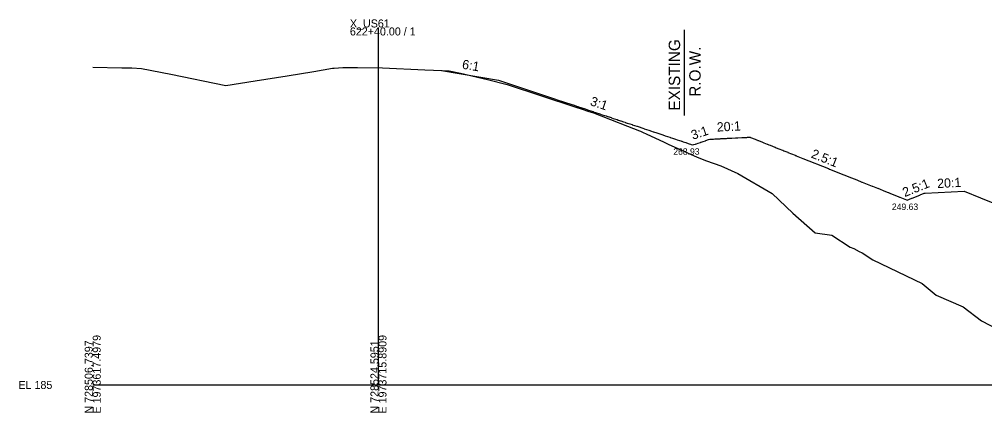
# Model space of a CAD drawing. Extents: x -26 to 1629, y -25 to 9635.
# Drawn here: x -25.7 to 312.2, y 5990.3 to 6127.8 of the extents above; entities that cross this region are included whole.
import ezdxf

# ---------------------------------------------------------------- set-up
doc = ezdxf.new("R2010")
doc.units = 0
for name, color, linetype in [('Default', 7, 'Continuous'), ('Draft_XS_Grid', 7, 'Continuous'), ('DTM CONTOURS_MAJOR', 7, 'Continuous'), ('DTM_X_GROUND', 7, 'Continuous'), ('XS_CELL', 7, 'Continuous'), ('XS_P_GROUND', 7, 'Continuous'), ('XS_P_TX_DCH', 7, 'Continuous'), ('XS_P_TX_FS_BS', 7, 'Continuous'), ('XS_X_ROW', 7, 'Continuous')]:
    doc.layers.add(name, color=color, linetype=linetype)

msp = doc.modelspace()

# ---------------------------------------------------------------- linework, layer by layer
at = {"layer": 'DTM_X_GROUND'}
msp.add_lwpolyline([(0, 6111.11), (10.2, 6110.92), (13.06, 6110.87), (13.65, 6110.85), (17.07, 6110.7), (27.36, 6108.64), (46.63, 6104.73), (56.89, 6106.31), (68.08, 6108.05), (77.42, 6109.59), (83.94, 6110.78), (84.49, 6110.81), (87.52, 6111), (92.64, 6110.94), (101.44, 6110.83), (116.19, 6110.19), (122.29, 6109.92), (124.75, 6109.8), (125.34, 6109.77), (128.7, 6109.01), (138.15, 6106.82), (138.16, 6106.81), (145.02, 6105.02), (169.03, 6097.18), (169.04, 6097.18), (171.3, 6096.44), (173.28, 6095.72), (175.2, 6095.1), (187.13, 6090.5), (191.38, 6088.82), (191.66, 6088.76), (192.43, 6088.39), (193.86, 6087.74), (199.8, 6084.97), (201.44, 6084.2), (211.49, 6079.7), (214.81, 6078.34), (219.83, 6076.62), (225.78, 6073.91), (237.78, 6066.91), (245.03, 6060.09), (252.79, 6053.2), (258.62, 6052.4), (265.04, 6048.19), (266.36, 6047.68), (268.26, 6046.69), (269.25, 6046.17), (272.97, 6043.73), (290.25, 6035.48), (295.22, 6031.45), (304.6, 6027.33), (311, 6022.42), (323.13, 6016.13)], dxfattribs=at)
at = {"layer": 'XS_CELL'}
for p, q in [((100, 6000), (100, 6125)), ((0, 6000), (100, 6000)), ((100, 6000), (550, 6000))]:
    msp.add_line(p, q, dxfattribs=at)
at = {"layer": 'XS_P_GROUND'}
for points in [[(122, 6109.93), (142, 6106.6)], [(142, 6106.6), (161.93, 6099.96), (162.54, 6099.75), (167.64, 6098.05), (167.65, 6098.05), (167.65, 6098.05), (168.04, 6097.92), (168.08, 6097.91), (169.61, 6097.4), (169.77, 6097.35), (169.96, 6097.28), (171.19, 6096.87), (171.9, 6096.63), (171.98, 6096.61), (173.46, 6096.11), (173.56, 6096.08), (175.09, 6095.57), (175.14, 6095.55), (175.16, 6095.55), (175.93, 6095.29), (175.97, 6095.28), (177.52, 6094.76), (177.65, 6094.72), (177.66, 6094.71), (178.32, 6094.49), (179.66, 6094.05), (179.92, 6093.96), (180.67, 6093.71), (180.72, 6093.69), (181.38, 6093.47), (181.41, 6093.46), (181.52, 6093.43), (182.13, 6093.22), (182.15, 6093.22), (182.18, 6093.21), (183.52, 6092.76), (183.53, 6092.76), (183.93, 6092.62), (183.95, 6092.62), (184.74, 6092.35), (184.78, 6092.34), (185.7, 6092.03), (186.28, 6091.84), (186.37, 6091.81), (187.04, 6091.59), (188, 6091.27), (188.76, 6091.01), (188.82, 6090.99), (190.38, 6090.47), (190.46, 6090.45), (190.52, 6090.43), (192.92, 6089.63), (192.96, 6089.61), (194.57, 6089.08), (194.61, 6089.06), (195.55, 6088.75), (196.13, 6088.56), (196.22, 6088.53), (196.56, 6088.41), (197.05, 6088.25), (199.21, 6087.53), (199.54, 6087.42), (200.34, 6087.15), (200.37, 6087.14), (201.98, 6086.61), (202.03, 6086.59), (202.06, 6086.58), (202.87, 6086.31), (202.95, 6086.28), (204, 6085.93), (204.54, 6085.75), (205.34, 6085.49), (205.38, 6085.47), (205.4, 6085.47), (205.82, 6085.33), (206.08, 6085.24), (206.22, 6085.2), (206.61, 6085.06), (207.05, 6084.92), (207.54, 6084.75), (207.77, 6084.68), (208.74, 6084.36), (209.23, 6084.19), (209.46, 6084.11), (210, 6083.93), (210.37, 6084.06), (210.42, 6084.07), (210.92, 6084.24), (211.15, 6084.32), (211.26, 6084.36), (211.88, 6084.56), (212.7, 6084.83), (212.83, 6084.88), (212.96, 6084.92), (213.58, 6085.13), (214.43, 6085.41), (214.52, 6085.44), (215.5, 6085.77), (215.91, 6085.9), (216, 6085.93), (216.08, 6085.94), (216.21, 6085.94), (217.2, 6085.99), (217.67, 6086.02), (217.9, 6086.03), (219.45, 6086.11), (219.59, 6086.11), (219.76, 6086.12), (220.47, 6086.16), (221.14, 6086.19), (221.27, 6086.2), (221.47, 6086.21), (221.74, 6086.22), (222.12, 6086.24), (222.33, 6086.25), (222.5, 6086.26), (222.79, 6086.27), (223.6, 6086.31), (223.66, 6086.32), (224.91, 6086.38), (225.73, 6086.42), (225.77, 6086.42), (225.82, 6086.42), (227.19, 6086.49), (227.27, 6086.5), (227.92, 6086.53), (227.99, 6086.53), (228.87, 6086.58), (229.17, 6086.59), (229.22, 6086.59), (229.66, 6086.62), (229.72, 6086.62), (229.82, 6086.62), (230, 6086.63), (230.09, 6086.6), (230.14, 6086.58), (231.83, 6085.9), (232.29, 6085.72), (232.3, 6085.72), (232.3, 6085.72), (232.7, 6085.55), (232.8, 6085.51), (233.01, 6085.43), (234.44, 6084.86), (234.83, 6084.7), (234.88, 6084.68), (236.08, 6084.2), (236.19, 6084.16), (236.58, 6084), (236.6, 6083.99), (237.04, 6083.82), (237.06, 6083.81), (238.75, 6083.14), (238.81, 6083.11), (239.18, 6082.96), (239.2, 6082.96), (239.22, 6082.95), (240.06, 6082.61), (240.1, 6082.6), (241.45, 6082.05), (241.46, 6082.05), (241.8, 6081.91), (241.83, 6081.9), (243.21, 6081.35), (243.28, 6081.32), (245.87, 6080.29), (245.88, 6080.28), (246.17, 6080.17), (246.22, 6080.14), (248.53, 6079.22), (257.49, 6075.64), (257.84, 6075.5), (257.89, 6075.48), (262.85, 6073.49), (262.91, 6073.47), (265.55, 6072.41), (265.57, 6072.4), (266.46, 6072.05), (266.48, 6072.04), (267.36, 6071.69), (267.41, 6071.67), (269.18, 6070.96), (269.27, 6070.93), (272.82, 6069.51), (272.86, 6069.49), (274.65, 6068.77), (274.71, 6068.75), (277.4, 6067.67), (277.42, 6067.66), (278.32, 6067.31), (278.46, 6067.25), (279, 6067.03), (279.24, 6066.94), (281.91, 6065.87), (282.38, 6065.68), (282.44, 6065.66), (284.79, 6064.72), (284.84, 6064.7), (285, 6064.63), (286.65, 6065.29), (286.72, 6065.32), (289.45, 6066.41), (289.53, 6066.45), (291, 6067.03), (291.35, 6067.05), (305, 6067.73), (310.65, 6065.47), (310.95, 6065.35), (343.33, 6052.4)]]:
    msp.add_lwpolyline(points, dxfattribs=at)
at = {"layer": 'XS_X_ROW'}
msp.add_line((207, 6124.17), (207, 6094.27), dxfattribs=at)

# ---------------------------------------------------------------- texts
at = {"layer": 'Default'}
msp.add_text('X', height=0.12, dxfattribs=at).set_placement((141.96, 6106.54))
at = {"layer": 'Draft_XS_Grid'}
msp.add_text('-', height=0.0001, dxfattribs=at).set_placement((0, 6000))
at = {"layer": 'DTM CONTOURS_MAJOR'}
for p in [(121.96, 6109.87), (141.96, 6106.54), (203.96, 6085.87), (215.96, 6085.87), (229.96, 6086.57), (209.96, 6083.87), (304.96, 6067.67), (278.96, 6066.97), (284.96, 6064.57), (290.96, 6066.97)]:
    msp.add_text('X', height=0.12, dxfattribs=at).set_placement(p)
at = {"layer": 'XS_CELL'}
for s, p in [('X_US61', (90, 6125)), ('622+40.00 / 1', (90, 6122.2)), ('EL 185', (-26, 5998.6))]:
    msp.add_text(s, height=2.8, dxfattribs=at).set_placement(p)
for s, p in [('E 1973617.4979', (2.8, 5990)), ('E 1973715.8909', (102.8, 5990)), ('N 728506.7397', (0, 5990)), ('N 728524.5951', (100, 5990))]:
    msp.add_text(s, height=2.8, rotation=90, dxfattribs=at).set_placement(p)
at = {"layer": 'XS_P_TX_DCH'}
for s, p in [('268.93', (203.17, 6080.48)), ('249.63', (279.67, 6061.18))]:
    msp.add_text(s, height=2.25, dxfattribs=at).set_placement(p)
at = {"layer": 'XS_P_TX_FS_BS'}
for s, rotation, p in [('6:1', 350.5377, (129.09, 6110.62)), ('3:1', 341.5651, (173.84, 6097.88)), ('20:1', 2.8624, (218.48, 6088.57)), ('3:1', 18.4349, (210.02, 6085.7)), ('2.5:1', 338.1986, (251.15, 6079.6)), ('2.5:1', 21.8014, (284.18, 6065.67)), ('20:1', 2.8624, (295.6, 6068.83))]:
    msp.add_text(s, height=3.24, rotation=rotation, dxfattribs=at).set_placement(p)
at = {"layer": 'XS_X_ROW'}
for s, p in [('EXISTING', (205.57, 6095.93)), ('R.O.W.', (212.77, 6100.77))]:
    msp.add_text(s, height=4, rotation=90, dxfattribs=at).set_placement(p)

doc.saveas('drawing.dxf')
